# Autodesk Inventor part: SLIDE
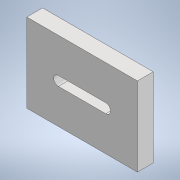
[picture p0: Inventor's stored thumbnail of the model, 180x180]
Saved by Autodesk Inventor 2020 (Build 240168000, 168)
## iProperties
Created: 2023-07
Part Number: SLIDE
Material: 일반
Document SubType Name: Modeling
Designer: chae-won
Density: 1 g/cm^3
Appearance: 기본값
Author: chae-won
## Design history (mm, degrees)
sketch "스케치1"
  geometry: L1 (-35, 25)-(35, 25); L2 (35, 25)-(35, -25); L3 (35, -25)-(-35, -25); L4 (-35, -25)-(-35, 25); L5 (-35, 25)-(35, -25); L6 (35, 25)-(-35, -25); 1 further point
  constraints: 12 end point, 2 midpoint, 2 parallel, 1 horizontal, 1 perpendicular
  dimensions: "d0" = 50 distance between parallel lines of L1 L3; "d1" = 70 distance between parallel lines of L2 L4
extrude "돌출1" new body sketch "스케치1" distance "d2" = 10; taper "d3" = 0 deg
sketch "스케치2"
  geometry: L1 (-15, 0)-(15, 0); L2 (-15, -3)-(15, -3); L3 (15, 3)-(-15, 3); A1 r 3 centre (-15, 0) between (-15, 3) and (-15, -3); A2 r 3 centre (15, 0) between (15, -3) and (15, 3); 1 further point
  constraints: 8 end point, 4 point on circle, 4 tangent, 2 centre point, 1 horizontal, 1 midpoint, 1 parallel
  dimensions: "d4" = 6 distance between parallel lines of L3 L2; "d5" = 30 distance of L1.start L1.end
extrude "돌출2" cut sketch "스케치2" extent not by distance; stored distance "d6" = 0; taper "d7" = 0 deg
node "솔리드1"
